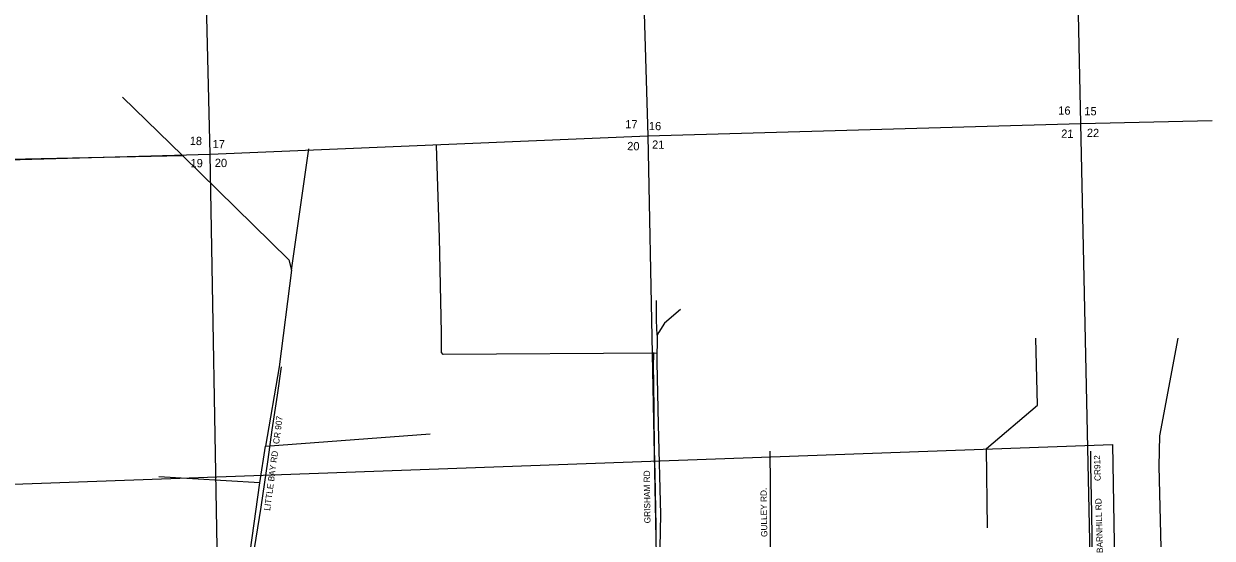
# Model space of a CAD drawing. Extents: x 1670563 to 1761545, y 515755 to 578944.
# Drawn here: x 1728380 to 1742760, y 545252 to 551478 of the extents above; entities that cross this region are included whole.
import ezdxf

# ---------------------------------------------------------------- set-up
doc = ezdxf.new("R2010")
doc.units = 0
for name, color, linetype in [('5_sectionlines', 7, 'Continuous'), ('62_text', 7, 'Continuous'), ('LIMITS', 7, 'Continuous'), ('SHP_LINE', 7, 'Continuous'), ('STREETCL', 7, 'Continuous'), ('STRNAMES', 7, 'Continuous')]:
    doc.layers.add(name, color=color, linetype=linetype)

# ---------------------------------------------------------------- blocks, each defined once
blk = doc.blocks.new('CITY_LIMITS02')
at = {"layer": 'LIMITS'}
for points in [[(1726692, 545851), (1741554, 546386)], [(1741554, 546386), (1741755, 534500)]]:
    blk.add_lwpolyline(points, dxfattribs=at)

msp = doc.modelspace()

# ---------------------------------------------------------------- linework, layer by layer
at = {"layer": '5_sectionlines'}
for points in [[(1741455, 534490), (1741315, 539804), (1741283, 545034), (1741171, 550270), (1741056, 555564), (1740936, 560833), (1740807, 565451)], [(1730876, 534163), (1730792, 539441), (1730728, 544689), (1730636, 549901), (1730504, 555211), (1730377, 560437), (1730252, 565363)], [(1735475, 565413), (1735705, 560624), (1735773, 555376), (1735929, 550122), (1736037, 544847), (1736085, 539630), (1736163, 534362)], [(1725455, 549754), (1730636, 549901), (1735929, 550122), (1741171, 550270), (1742760, 550307)]]:
    msp.add_lwpolyline(points, dxfattribs=at)
at = {"layer": 'SHP_LINE'}
for points in [[(1723245, 550912), (1724146, 550446), (1725400, 549818), (1725548, 549785), (1730299, 549885)], [(1729574, 550589), (1730299, 549885)], [(1731618, 548497), (1731828, 549966)], [(1736039, 547492), (1733455, 547475), (1733434, 547501), (1733434, 547738), (1733411, 548889), (1733372, 550005)], [(1730299, 549885), (1731587, 548620), (1731618, 548497)], [(1731618, 548497), (1731469, 547325), (1731305, 546367)], [(1736042, 547708), (1736034, 547888), (1736036, 548128)], [(1736324, 548021), (1736133, 547853), (1736062, 547748), (1736042, 547708)], [(1736042, 547708), (1736038, 547384), (1736056, 546628), (1736085, 545539), (1736071, 544937)], [(1740039, 545378), (1740029, 546338), (1740646, 546863), (1740626, 547672)], [(1742345, 547672), (1742122, 546490), (1742112, 546126), (1742138, 545137), (1742143, 544772), (1741880, 542983), (1741870, 542549), (1741910, 542482)], [(1731305, 546367), (1733298, 546516)], [(1731235, 545924), (1731305, 546367)], [(1731235, 545924), (1730012, 545995)], [(1731073, 544766), (1731235, 545924)]]:
    msp.add_lwpolyline(points, dxfattribs=at)
at = {"layer": 'STREETCL'}
for points in [[(1735999, 547500), (1735997, 547315), (1735998, 547148), (1736004, 546765), (1736009, 546334), (1736016, 546023), (1736026, 545397), (1736028, 545264), (1736028, 545256), (1736028, 545249)], [(1731493, 547328), (1731444, 546984), (1731381, 546565), (1731333, 546207), (1731249, 545629), (1731169, 545127)], [(1737428, 544898), (1737417, 545118), (1737415, 545160), (1737414, 545203), (1737413, 545900), (1737410, 546305)], [(1741313, 544999), (1741302, 545553), (1741291, 546138), (1741291, 546305)]]:
    msp.add_lwpolyline(points, dxfattribs=at)

# ---------------------------------------------------------------- block references
msp.add_blockref('CITY_LIMITS02', (0, 0), dxfattribs=at)

# ---------------------------------------------------------------- texts
at = {"layer": '62_text'}
for s, rotation, p in [('16', 358.93, (1740896, 550380)), ('15', 358.93, (1741212, 550372)), ('17', 358.93, (1735657, 550214)), ('16', 358.93, (1735943, 550192)), ('21', 358.93, (1740932, 550099)), ('22', 358.93, (1741242, 550109)), ('18', 358.9301, (1730387, 550012)), ('17', 358.9301, (1730664, 549974)), ('21', 358.9301, (1735981, 549967)), ('20', 358.9301, (1735680, 549949)), ('19', 358.9301, (1730396, 549743)), ('20', 358.9301, (1730690, 549746))]:
    msp.add_text(s, height=100, rotation=rotation, dxfattribs=at).set_placement(p)
at = {"layer": 'STRNAMES'}
for s, rotation, p in [('LITTLE BAY RD   CR 907', 82.349, (1731360, 545582)), ('CR912', 91.6178, (1741411, 545946)), ('GRISHAM RD', 90.7315, (1735963, 545433)), ('GULLEY RD.', 90.8956, (1737377, 545268)), ('BARNHILL RD', 91.6178, (1741438, 545074))]:
    msp.add_text(s, height=75, rotation=rotation, dxfattribs=at).set_placement(p)

doc.saveas('drawing.dxf')
